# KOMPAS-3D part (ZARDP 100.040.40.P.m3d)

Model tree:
1. Операция без истории:1
2. Операция без истории:2
3. Операция без истории:3
4. Операция без истории:4
5. Операция без истории:5
6. Операция без истории:6
7. Операция без истории:7
8. Операция без истории:8
9. Операция без истории:9
10. Операция без истории:10
11. Операция без истории:11
12. Операция без истории:12
13. Операция без истории:13
14. Операция без истории:14
15. Операция без истории:15
16. Операция без истории:16
17. Операция без истории:17
18. Операция без истории:18
19. Операция без истории:19
20. Операция без истории:20
21. Операция без истории:21
22. Операция без истории:22
23. Операция без истории:23
24. Операция без истории:24
25. Операция без истории:25
26. Операция без истории:26
27. Операция без истории:27
28. Операция без истории:28
29. Операция без истории:29
30. Операция без истории:30
31. Операция без истории:31
32. Операция без истории:32
33. Операция без истории:33
34. Операция без истории:34
35. Операция без истории:35

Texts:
  ЗАРДП 100.040.40-XX.Р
